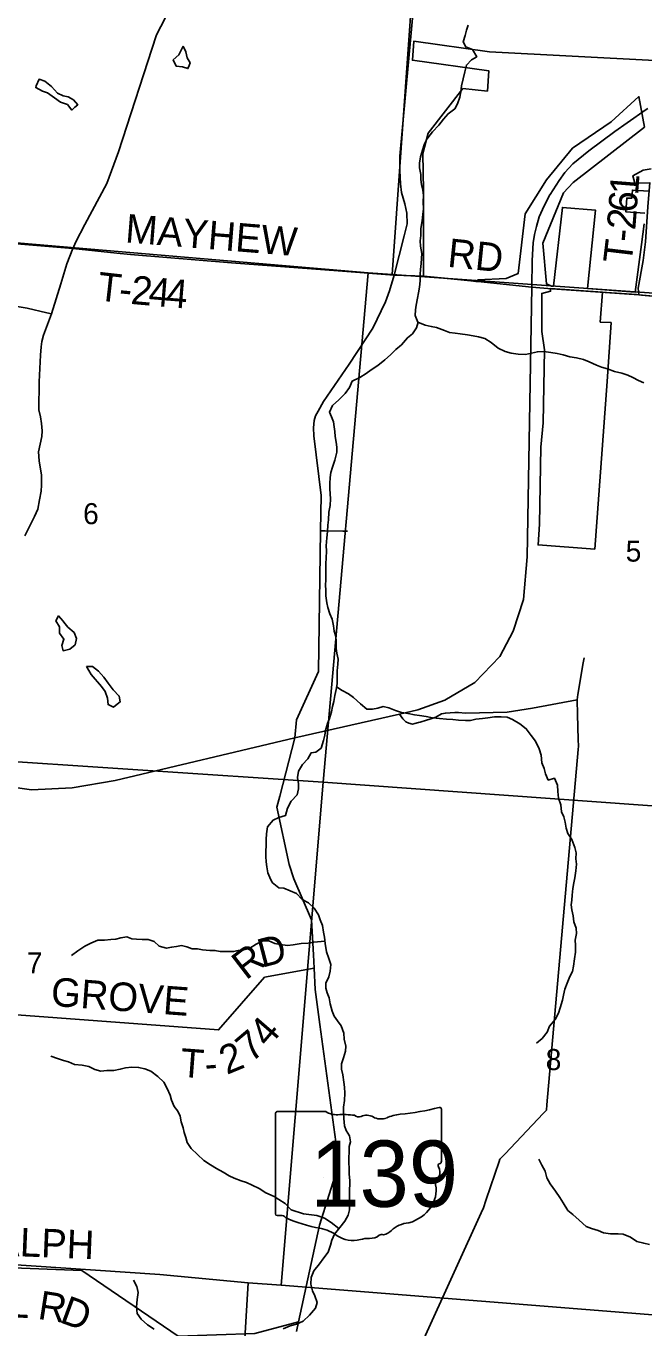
# Model space of a CAD drawing. Extents: x 1715311 to 2083412, y 146837 to 553079.
# Drawn here: x 1922693 to 1929182, y 363016 to 376689 of the extents above; entities that cross this region are included whole.
import ezdxf

# ---------------------------------------------------------------- set-up
doc = ezdxf.new("R2010")
doc.units = 0
for name, color, linetype in [('GM_X_Corporation', 7, 'Continuous'), ('GM_X_County_Road', 7, 'Continuous'), ('GM_X_Minor_Lake', 7, 'Continuous'), ('GM_X_Minor_River', 7, 'Continuous'), ('GM_X_Section', 7, 'Continuous'), ('GM_X_Section_Text', 7, 'Continuous'), ('GM_X_State_Location', 7, 'Continuous'), ('GM_X_State_Route', 7, 'Continuous'), ('GM_X_State_Shield', 7, 'Continuous'), ('GM_X_Township', 7, 'Continuous'), ('GM_X_Township_Road', 7, 'Continuous'), ('GM_X_Township_Road_Text', 7, 'Continuous'), ('GM_X_Township_ROW', 7, 'Continuous')]:
    doc.layers.add(name, color=color, linetype=linetype)

msp = doc.modelspace()

# ---------------------------------------------------------------- linework, layer by layer
at = {"layer": 'GM_X_Corporation'}
for points in [[(1929185, 374612), (1929157, 374393), (1929089, 373894), (1928589, 373933), (1928674, 374754), (1928325, 374784), (1928233, 373957), (1928212, 373957), (1928160, 373981), (1928121, 374407), (1928337, 374938), (1928437, 375046), (1929188, 375628), (1929129, 375948), (1928836, 375684), (1928430, 375405), (1928159, 375073), (1927935, 374717), (1927860, 374088), (1927736, 374038), (1927436, 374022), (1927436, 374006), (1927263, 374022), (1926868, 374061), (1926868, 374303), (1926868, 374963), (1926861, 375351), (1926914, 375564), (1927281, 376032), (1927538, 376005), (1927553, 376217), (1926750, 376330), (1926764, 376529), (1927559, 376418), (1929297, 376326)], [(1929256, 375190), (1929174, 375176), (1929065, 375115), (1929085, 375038), (1929244, 375043)], [(1929237, 374954), (1929060, 374966), (1929053, 374880), (1929001, 374882), (1928993, 374736), (1929192, 374722)]]:
    msp.add_lwpolyline(points, dxfattribs=at)
msp.add_lwpolyline([(1928202, 373931), (1928746, 373893), (1928723, 373580), (1928836, 373574), (1928797, 372957), (1928665, 371196), (1928070, 371240), (1928084, 371458), (1928098, 372265), (1928122, 372522), (1928137, 373287), (1928111, 373479), (1928108, 373880), (1928202, 373903)], close=True, dxfattribs=at)
at = {"layer": 'GM_X_County_Road'}
for points in [[(1923193, 374373), (1923215, 374422), (1923311, 374606), (1923540, 375036), (1923665, 375367), (1924059, 376586), (1924062, 376595), (1924107, 376683), (1924621, 377695), (1924772, 378010), (1924849, 378203), (1924915, 378357), (1925013, 378572), (1925086, 378707), (1925208, 378930), (1925231, 378971)], [(1922680, 371335), (1922782, 371536), (1922815, 371614), (1922834, 371711), (1922853, 371804), (1922855, 371867), (1922855, 371973), (1922830, 372122), (1922825, 372218), (1922857, 372377), (1922862, 372438), (1922856, 372516), (1922845, 372583), (1922828, 372659), (1922830, 372951), (1922846, 373231), (1922850, 373319), (1922859, 373375), (1922875, 373442), (1922959, 373665), (1923059, 373980), (1923121, 374191), (1923184, 374353), (1923193, 374373)]]:
    msp.add_lwpolyline(points, dxfattribs=at)
at = {"layer": 'GM_X_Minor_Lake'}
for points in [[(1924344, 376478), (1924296, 376386), (1924238, 376334), (1924270, 376267), (1924336, 376261), (1924392, 376241), (1924404, 376273)], [(1924404, 376273), (1924416, 376301), (1924386, 376353), (1924372, 376418), (1924344, 376478)], [(1922799, 376061), (1922795, 376043), (1922865, 376003), (1922917, 375987), (1922991, 375933), (1923055, 375889), (1923127, 375864), (1923174, 375806), (1923206, 375835)], [(1923206, 375835), (1923236, 375862), (1923191, 375912), (1923135, 375945), (1923083, 375955), (1923023, 375983), (1922961, 376053), (1922891, 376109), (1922829, 376129), (1922799, 376061)], [(1923090, 370428), (1923083, 370437), (1923032, 370493), (1923004, 370441), (1923045, 370379), (1923043, 370311), (1923091, 370248), (1923067, 370182), (1923081, 370128), (1923151, 370146)], [(1923151, 370146), (1923207, 370190), (1923223, 370256), (1923197, 370320), (1923133, 370375), (1923090, 370428)], [(1923329, 369964), (1923378, 369878), (1923486, 369753), (1923524, 369699), (1923548, 369631), (1923554, 369563), (1923612, 369535), (1923651, 369568)], [(1923651, 369568), (1923680, 369591), (1923672, 369651), (1923608, 369719), (1923556, 369787), (1923508, 369852), (1923454, 369912), (1923392, 369962), (1923329, 369964)]]:
    msp.add_lwpolyline(points, dxfattribs=at)
at = {"layer": 'GM_X_Minor_River'}
for points in [[(1927335, 376699), (1927319, 376645), (1927303, 376589), (1927284, 376523), (1927310, 376469), (1927382, 376442), (1927425, 376366), (1927369, 376332), (1927317, 376278), (1927300, 376206), (1927267, 376059), (1927259, 375998), (1927248, 375940), (1927224, 375871), (1927194, 375819), (1927125, 375767), (1927077, 375709), (1927027, 375648), (1926962, 375576), (1926902, 375502), (1926877, 375450), (1926855, 375384), (1926835, 375314), (1926826, 375248), (1926826, 375198), (1926839, 375128), (1926837, 375076), (1926847, 375024), (1926860, 374966), (1926866, 374908), (1926863, 374846), (1926865, 374764), (1926860, 374712), (1926854, 374642), (1926839, 374564), (1926837, 374487), (1926833, 374433), (1926836, 374375), (1926848, 374299), (1926847, 374247), (1926843, 374195), (1926836, 374133), (1926830, 374081), (1926830, 374013), (1926823, 373947), (1926815, 373885), (1926804, 373829), (1926788, 373757), (1926784, 373707), (1926779, 373649), (1926807, 373579), (1926884, 373546), (1926948, 373534), (1927002, 373521), (1927086, 373491), (1927140, 373470), (1927198, 373462), (1927253, 373455), (1927327, 373445), (1927387, 373436), (1927443, 373426), (1927509, 373408), (1927578, 373365), (1927650, 373305), (1927726, 373272), (1927789, 373252), (1927861, 373241), (1927937, 373239), (1928001, 373254), (1928063, 373268), (1928131, 373271)], [(1926811, 373577), (1926794, 373519), (1926750, 373457), (1926698, 373415), (1926635, 373339), (1926575, 373292), (1926519, 373234), (1926460, 373182), (1926388, 373123), (1926316, 373077), (1926266, 373039), (1926197, 372996), (1926117, 372958), (1926089, 372892), (1926044, 372829), (1925978, 372763), (1925912, 372703), (1925881, 372634), (1925899, 372583), (1925920, 372531), (1925930, 372479), (1925934, 372429), (1925939, 372377), (1925951, 372317), (1925957, 372265), (1925958, 372212), (1925936, 372129), (1925911, 372057), (1925895, 371999), (1925885, 371947), (1925884, 371885), (1925884, 371828), (1925885, 371774), (1925889, 371724), (1925885, 371652), (1925872, 371582), (1925868, 371502), (1925863, 371446), (1925857, 371380), (1925850, 371312), (1925846, 371228), (1925847, 371178), (1925843, 371100), (1925840, 371044), (1925840, 370988), (1925842, 370934), (1925841, 370874), (1925839, 370816), (1925841, 370765), (1925840, 370703), (1925850, 370631), (1925861, 370581), (1925883, 370517), (1925906, 370459), (1925920, 370388), (1925929, 370334), (1925945, 370276), (1925951, 370224), (1925950, 370152), (1925958, 370102), (1925969, 370038), (1925967, 369988), (1925961, 369916), (1925960, 369779), (1925949, 369721), (1925937, 369657), (1925924, 369595), (1925910, 369541), (1925900, 369487), (1925881, 369415), (1925859, 369364), (1925836, 369292), (1925830, 369242), (1925818, 369184), (1925793, 369106), (1925737, 369064), (1925687, 369056), (1925653, 368994), (1925596, 368933), (1925554, 368863), (1925543, 368795), (1925555, 368729), (1925553, 368677), (1925540, 368615), (1925478, 368547), (1925439, 368473), (1925417, 368397), (1925349, 368376), (1925287, 368348), (1925228, 368278), (1925218, 368206), (1925215, 368146), (1925215, 368078), (1925210, 368026), (1925210, 367966), (1925216, 367910), (1925221, 367858), (1925231, 367796), (1925253, 367746), (1925278, 367695), (1925348, 367639)], [(1928131, 373271), (1928203, 373261), (1928271, 373248), (1928335, 373234), (1928403, 373215), (1928474, 373203), (1928546, 373186), (1928608, 373162), (1928684, 373127), (1928736, 373107), (1928799, 373089), (1928873, 373062), (1928951, 373042), (1929013, 373021), (1929066, 372997), (1929126, 372966), (1929182, 372942)], [(1925954, 369749), (1926013, 369711), (1926079, 369676), (1926133, 369636), (1926204, 369572), (1926272, 369515), (1926331, 369513), (1926388, 369524), (1926444, 369542), (1926501, 369527), (1926571, 369501), (1926637, 369481), (1926705, 369468), (1926771, 369456), (1926825, 369449), (1926894, 369439), (1926960, 369424), (1927036, 369416), (1927108, 369409), (1927176, 369405), (1927234, 369400), (1927308, 369394), (1927360, 369396), (1927416, 369409), (1927486, 369417), (1927542, 369422), (1927614, 369434), (1927682, 369433), (1927747, 369429), (1927803, 369407), (1927877, 369362), (1927946, 369308), (1927998, 369239), (1928043, 369179), (1928081, 369096), (1928104, 369030), (1928108, 368952), (1928133, 368890), (1928149, 368834), (1928177, 368769), (1928241, 368789), (1928274, 368715), (1928276, 368649), (1928285, 368578), (1928309, 368510), (1928316, 368436), (1928340, 368384), (1928355, 368328), (1928365, 368265), (1928382, 368209), (1928424, 368145), (1928455, 368063), (1928469, 368004), (1928467, 367944), (1928472, 367886), (1928468, 367816), (1928455, 367742), (1928447, 367690), (1928436, 367630), (1928428, 367562), (1928424, 367508), (1928417, 367458), (1928423, 367408), (1928437, 367344), (1928444, 367280), (1928470, 367213), (1928475, 367159), (1928461, 367087), (1928462, 367037), (1928464, 366963), (1928453, 366891), (1928441, 366815), (1928433, 366761), (1928404, 366707), (1928376, 366637), (1928351, 366575), (1928337, 366511), (1928325, 366457), (1928302, 366379), (1928284, 366322), (1928251, 366254), (1928189, 366186), (1928164, 366122), (1928112, 366056), (1928054, 366007)], [(1925348, 367639), (1925400, 367636), (1925465, 367608), (1925533, 367580), (1925593, 367517), (1925660, 367481), (1925720, 367424), (1925763, 367354), (1925783, 367303), (1925807, 367241), (1925816, 367173), (1925826, 367119), (1925835, 367053), (1925849, 366965), (1925872, 366896), (1925892, 366832), (1925887, 366762), (1925871, 366704), (1925842, 366636), (1925842, 366584), (1925854, 366534), (1925877, 366484), (1925887, 366418), (1925906, 366343), (1925928, 366291), (1925962, 366241), (1926001, 366189), (1926029, 366112), (1926032, 366048), (1926050, 365974), (1926047, 365924), (1926025, 365854), (1926004, 365788), (1926006, 365734), (1926020, 365674), (1926029, 365596), (1926037, 365546), (1926040, 365483), (1926036, 365403), (1926025, 365333), (1926025, 365279), (1926031, 365217), (1926038, 365139), (1926056, 365089), (1926091, 365035), (1926101, 364972), (1926086, 364920), (1926086, 364858), (1926084, 364808), (1926083, 364758), (1926085, 364686), (1926086, 364632), (1926092, 364566), (1926091, 364428), (1926089, 364370), (1926090, 364256)], [(1925831, 367079), (1925715, 367066), (1925657, 367058), (1925583, 367052), (1925499, 367041), (1925437, 367033), (1925362, 367042), (1925306, 367054), (1925244, 367083), (1925178, 367081), (1925108, 367048), (1925042, 367006), (1924978, 366988), (1924922, 366981), (1924872, 366969), (1924810, 366970), (1924730, 366970), (1924676, 366980), (1924624, 366979), (1924546, 366987), (1924494, 366996), (1924438, 366998), (1924380, 367020), (1924325, 367031), (1924273, 367023), (1924221, 367014), (1924169, 367006), (1924091, 367026), (1924039, 367075), (1923975, 367095), (1923911, 367096), (1923854, 367098), (1923802, 367104), (1923750, 367123), (1923688, 367113), (1923636, 367100), (1923582, 367094), (1923516, 367088), (1923448, 367087), (1923374, 367057), (1923310, 367026), (1923237, 366976), (1923169, 366928)], [(1925477, 364258), (1925415, 364322), (1925349, 364365), (1925298, 364397), (1925210, 364436), (1925140, 364482), (1925067, 364517), (1925007, 364545), (1924953, 364562), (1924879, 364588), (1924826, 364612), (1924762, 364651), (1924694, 364689), (1924629, 364728), (1924561, 364776), (1924494, 364839), (1924428, 364900), (1924384, 364962), (1924369, 365016), (1924353, 365068), (1924342, 365118), (1924322, 365181), (1924310, 365241), (1924285, 365291), (1924249, 365341), (1924220, 365408), (1924206, 365460), (1924175, 365532), (1924141, 365598), (1924078, 365657), (1924004, 365711), (1923940, 365738), (1923874, 365752), (1923802, 365755), (1923738, 365747), (1923682, 365732), (1923614, 365720), (1923542, 365718), (1923479, 365713), (1923415, 365729), (1923351, 365762), (1923283, 365774), (1923203, 365781), (1923138, 365809), (1923086, 365824), (1923022, 365844), (1922954, 365871)], [(1928382, 364251), (1928334, 364331), (1928297, 364385), (1928253, 364453), (1928196, 364528), (1928162, 364594), (1928145, 364662), (1928109, 364725), (1928077, 364789)], [(1926090, 364256), (1926076, 364201), (1926042, 364139), (1925988, 364071), (1925933, 364002), (1925905, 363938), (1925891, 363884), (1925865, 363812), (1925821, 363752), (1925776, 363690), (1925716, 363614), (1925688, 363546), (1925684, 363476), (1925700, 363404), (1925727, 363352), (1925749, 363284), (1925731, 363222), (1925671, 363150), (1925602, 363086), (1925534, 363056), (1925468, 363037), (1925392, 363007)], [(1925978, 364059), (1925896, 364124), (1925826, 364168), (1925746, 364196), (1925606, 364215), (1925477, 364258)], [(1929241, 363893), (1929179, 363905), (1929107, 363925), (1929041, 363968), (1928964, 364000), (1928910, 364004), (1928830, 364004), (1928758, 364015), (1928702, 364041), (1928630, 364061), (1928576, 364081), (1928501, 364148), (1928435, 364206), (1928382, 364251)], [(1924038, 363002), (1923968, 363050), (1923903, 363107), (1923861, 363169), (1923851, 363237), (1923860, 363315), (1923870, 363387), (1923856, 363451), (1923820, 363517)]]:
    msp.add_lwpolyline(points, dxfattribs=at)
at = {"layer": 'GM_X_Section'}
for points in [[(1920992, 379866), (1926912, 379354), (1926539, 374078), (1926287, 374098), (1920578, 374582)], [(1926912, 379354), (1932428, 379000), (1932139, 373684), (1931589, 373720), (1926539, 374078)], [(1926287, 374098), (1925814, 368747), (1920128, 369127), (1920180, 369801), (1920578, 374582)], [(1926539, 374078), (1931589, 373720), (1931068, 368370), (1925814, 368747), (1926287, 374098)], [(1920128, 369127), (1925814, 368747), (1925372, 363465), (1925024, 363490), (1924098, 363576), (1919728, 363870), (1919771, 364505)], [(1925814, 368747), (1931068, 368370), (1930676, 363042), (1925372, 363465)], [(1919728, 363870), (1924098, 363576), (1925024, 363490), (1924860, 360738), (1924867, 358127), (1919300, 358705), (1919330, 358987)], [(1925024, 363490), (1925372, 363465), (1930676, 363042), (1930990, 363014), (1930593, 357858), (1924867, 358127), (1924860, 360738)]]:
    msp.add_lwpolyline(points, close=True, dxfattribs=at)
at = {"layer": 'GM_X_State_Route'}
for points in [[(1925532, 362978), (1925554, 363081), (1925653, 363530), (1925776, 364094), (1925976, 364738), (1925779, 366204), (1925729, 366569), (1925718, 366796), (1925711, 366935), (1925692, 367302), (1925504, 367734), (1925456, 367883), (1925328, 368485), (1925358, 368601), (1925517, 369212), (1925533, 369402), (1925765, 369910), (1925786, 371388), (1925791, 371758), (1925715, 372384), (1925710, 372470), (1925720, 372546), (1925732, 372594), (1925760, 372645), (1925815, 372745), (1926087, 373137), (1926333, 373517), (1926466, 373793), (1926511, 373908), (1926560, 374073), (1926664, 374484), (1926695, 374612), (1926690, 374725), (1926671, 374822), (1926636, 374941), (1926624, 375033), (1926617, 375173), (1926619, 375321), (1926769, 376960)], [(1929004, 375671), (1929205, 375811), (1929221, 375823)], [(1928198, 374921), (1928293, 375067), (1928350, 375150), (1928436, 375243), (1928603, 375378), (1928875, 375581), (1929004, 375671)], [(1925517, 369212), (1926616, 369463), (1926807, 369507), (1927091, 369609), (1927404, 369794), (1927667, 370067), (1927808, 370335), (1927918, 370667), (1927954, 371113), (1928004, 373947), (1928009, 374226), (1928019, 374412), (1928034, 374499), (1928053, 374582), (1928082, 374686), (1928134, 374800), (1928194, 374915), (1928198, 374921)], [(1915572, 367954), (1915902, 368092), (1916489, 368357), (1917449, 368842), (1919070, 369620), (1919346, 369719), (1919582, 369782), (1919778, 369800), (1919970, 369806), (1920186, 369777), (1920326, 369751), (1920545, 369682), (1920773, 369584), (1921110, 369382), (1921759, 369016), (1922096, 368840), (1922399, 368716), (1922751, 368667), (1923177, 368689), (1923627, 368765), (1925517, 369212)]]:
    msp.add_lwpolyline(points, dxfattribs=at)
at = {"layer": 'GM_X_State_Shield'}
for p, q in [((1925314, 365270), (1925314, 364214)), ((1925841, 365288), (1925331, 365288)), ((1927054, 364762), (1927054, 365315)), ((1927054, 364762), (1927054, 364762))]:
    msp.add_line(p, q, dxfattribs=at)
for centre, major_axis, start_param, end_param in [((1925334, 365273), (20.2, 0), 1.712693, 3.28349), ((1925962, 365411), (196, 0), 4.042523, 4.731795), ((1926027, 364695), (702, 0), 1.404758, 1.657858), ((1926186, 365278), (56.4, 0), 3.836095, 5.185415), ((1926269, 365156), (117, 0), 0.950623, 2.079405), ((1926420, 365323), (141, 0), 4.081561, 5.145723), ((1926670, 364966), (371, 0), 1.699011, 2.107814), ((1926434, 366729), (1845, 0), 4.814394, 5.042369), ((1927035, 365317), (19.4, 0), 6.141152, 7.989035), ((1927050, 364721), (30, 0), 1.883978, 3.671073), ((1926859, 364651), (180, 0), 5.934695, 6.695948), ((1927033, 364760), (20.7, 0), 5.05454, 6.418171), ((1926538, 364460), (462, 0), 5.101752, 6.440018), ((1927124, 364531), (131, 0), 2.387724, 3.262537), ((1925334, 364211), (20.3, 0), 3.00124, 4.508301), ((1925337, 364319), (155, 0), 4.665946, 4.897461), ((1925369, 364153), (56, 0), 0.519207, 1.627899), ((1926075, 365102), (1333, 0), 4.195997, 4.488961), ((1926732, 363917), (253, 0), 1.647645, 2.488434), ((1925678, 363739), (417, 0), 0.823519, 1.323587), ((1926129, 364147), (265, 0), 4.026481, 4.996735), ((1926301, 364068), (141, 0), 4.691044, 5.507374), ((1926429, 363966), (39.7, 0), 1.147584, 2.315152), ((1926412, 364111), (149, 0), 4.937069, 5.64225), ((1926282, 363782), (217, 0), 1.495662, 1.94098)]:
    msp.add_ellipse(centre, major_axis=major_axis, ratio=0.8, start_param=start_param, end_param=end_param, dxfattribs=at)
at = {"layer": 'GM_X_Township'}
for points in [[(1920583, 374570), (1923184, 374353), (1923645, 374304), (1923790, 374289), (1924849, 374203), (1925971, 374118), (1926560, 374073), (1926868, 374061), (1927436, 374006), (1928004, 373947), (1928213, 373930), (1929127, 373866), (1929585, 373824), (1930336, 373780), (1931574, 373721), (1932048, 373697), (1933153, 373603), (1933404, 373578), (1934284, 373507), (1934765, 373455), (1936669, 373249), (1937122, 373218), (1942174, 372734)], [(1942174, 372734), (1937122, 373218), (1936669, 373249), (1934765, 373455), (1934284, 373507), (1933404, 373578), (1933153, 373603), (1932048, 373697), (1931574, 373721), (1930336, 373780), (1929585, 373824), (1929127, 373866), (1928213, 373930), (1928004, 373947), (1927436, 374006), (1926868, 374061), (1926560, 374073), (1925971, 374118), (1924849, 374203), (1923790, 374289), (1923645, 374304), (1923184, 374353), (1920583, 374570)]]:
    msp.add_lwpolyline(points, dxfattribs=at)
at = {"layer": 'GM_X_Township_Road'}
for points in [[(1929127, 373866), (1929120, 373937), (1929173, 374225), (1929198, 374422), (1929223, 374791), (1929244, 375044)], [(1923184, 374353), (1923645, 374304), (1923790, 374289), (1924849, 374202), (1925971, 374118), (1926560, 374073)], [(1926560, 374073), (1926775, 374065)], [(1926775, 374065), (1926868, 374061), (1927310, 374018)], [(1927310, 374018), (1927417, 374007)], [(1927417, 374007), (1927436, 374006), (1928004, 373947), (1928213, 373930), (1928213, 373930)], [(1928213, 373930), (1928737, 373893)], [(1928737, 373893), (1929103, 373868)], [(1929103, 373868), (1929127, 373866), (1929155, 373863)], [(1929155, 373863), (1929585, 373824), (1930336, 373780), (1931574, 373721), (1932048, 373697), (1933153, 373603), (1933404, 373578), (1934284, 373507)], [(1925786, 371388), (1925833, 371387), (1926021, 371384), (1926068, 371383)], [(1928479, 369612), (1928488, 369668), (1928544, 370000), (1928553, 370055)], [(1926551, 362201), (1927491, 364265), (1927492, 364266), (1927526, 364364), (1927662, 364764), (1927670, 364787), (1927726, 364846), (1928123, 365268), (1928158, 365304), (1928163, 365360), (1928492, 369090), (1928495, 369127), (1928492, 369195), (1928484, 369458), (1928479, 369612), (1928012, 369525), (1927744, 369484), (1927309, 369474), (1927233, 369478)], [(1927233, 369478), (1927233, 369478), (1927197, 369479), (1927096, 369474), (1927056, 369464), (1926995, 369429), (1926934, 369408), (1926899, 369398), (1926833, 369378), (1926813, 369373), (1926777, 369363), (1926752, 369358), (1926712, 369368), (1926681, 369383), (1926651, 369413), (1926616, 369463)], [(1925718, 366796), (1925198, 366700), (1924715, 366146), (1922170, 366336), (1921417, 366845), (1921133, 367095), (1920771, 367333), (1920694, 367371), (1920613, 367387), (1920486, 367387), (1920349, 367378)], [(1925554, 363081), (1925096, 362956), (1924290, 362930), (1923279, 363620), (1921733, 363680), (1921019, 364066)]]:
    msp.add_lwpolyline(points, dxfattribs=at)
at = {"layer": 'GM_X_Township_ROW'}
msp.add_lwpolyline([(1921625, 374269), (1921642, 374303), (1921759, 374353), (1921825, 374311), (1921858, 374161), (1921900, 374094), (1922122, 373855), (1922198, 373816), (1922288, 373791), (1922493, 373760), (1922704, 373724), (1922912, 373676), (1922959, 373665)], dxfattribs=at)

# ---------------------------------------------------------------- texts
at = {"layer": 'GM_X_Section_Text'}
for s, p in [('6', (1923292, 371457)), ('5', (1928990, 371064)), ('7', (1922701, 366739)), ('8', (1928150, 365724))]:
    msp.add_text(s, height=221, rotation=0, dxfattribs=at).set_placement(p)
at = {"layer": 'GM_X_State_Location'}
for s in ['s', 'r']:
    msp.add_text(s, height=1, dxfattribs=at).set_placement((1926164, 364672))
msp.add_text('139', height=1, rotation=0, dxfattribs=at).set_placement((1925811, 364599))
at = {"layer": 'GM_X_State_Shield'}
msp.add_text('139', height=696.1, dxfattribs=at).set_placement((1925677, 364288))
at = {"layer": 'GM_X_Township_Road_Text'}
for s, rotation, p in [('1', 85.568, (1929119, 374906)), ('6', 85.5637, (1929104, 374723)), ('MAYHEW', 355.3966, (1923728, 374417)), ('2', 85.4371, (1929090, 374540)), ('-', 84.5657, (1929078, 374413)), ('RD', 354.0783, (1927111, 374161)), ('T', 83.1828, (1929050, 374183)), ('T', 353.5278, (1923432, 373809)), ('2', 354.8882, (1923785, 373771)), ('4', 355.2698, (1923972, 373754)), ('4', 355.3691, (1924156, 373739)), ('-', 354.465, (1923660, 373783)), ('D', 14.6839, (1925170, 366798)), ('R', 37.5412, (1925003, 366662)), ('GROVE', 355.7495, (1922947, 366400)), ('4', 49.0848, (1925235, 365950)), ('7', 40.1844, (1925057, 365795)), ('T', 355.6822, (1924304, 365655)), ('2', 22.3835, (1924800, 365672)), ('-', 4.5826, (1924579, 365638)), ('RALPH', 357.6931, (1922067, 363791)), ('L', 357.2733, (1922499, 363130)), ('R', 351.0651, (1922807, 363113)), ('D', 339.8115, (1923035, 363079))]:
    msp.add_text(s, height=300, rotation=rotation, dxfattribs=at).set_placement(p)

doc.saveas('drawing.dxf')
